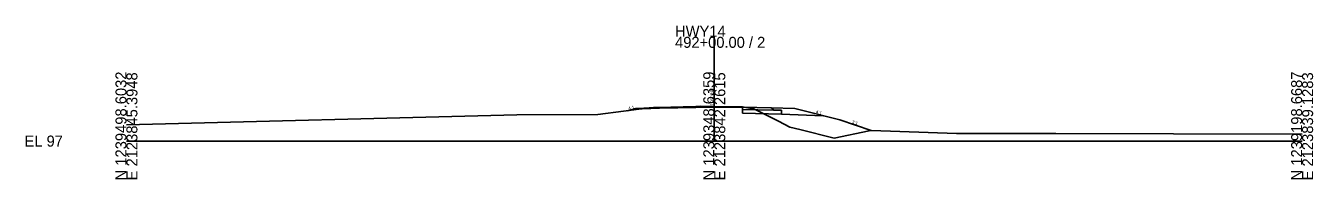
# Model space of a CAD drawing. Extents: x -26 to 303, y -10 to 11521.
# Drawn here: x -25.7 to 302.8, y 3490.3 to 3529.3 of the extents above; entities that cross this region are included whole.
import ezdxf

# ---------------------------------------------------------------- set-up
doc = ezdxf.new("R2010")
doc.units = 0
for name, color, linetype in [('XS_CELL', 7, 'Continuous'), ('XS_P_FINISHED_GRADE', 7, 'Continuous'), ('XS_P_SUBGRADE_GRANULAR', 7, 'Continuous'), ('XS_P_SUBGRADE_LEVELING', 7, 'Continuous'), ('XS_P_SUBGRADE_PAVEMENT', 7, 'Continuous'), ('XS_P_TX_FS_BS', 7, 'Continuous'), ('XS_X_GROUND', 7, 'Continuous'), ('XS_X_GROUND_TX', 7, 'Continuous')]:
    doc.layers.add(name, color=color, linetype=linetype)

msp = doc.modelspace()

# ---------------------------------------------------------------- linework, layer by layer
at = {"layer": 'XS_CELL'}
for p, q in [((150, 3500), (150, 3526.52)), ((0, 3500), (150, 3500)), ((150, 3500), (300, 3500))]:
    msp.add_line(p, q, dxfattribs=at)
at = {"layer": 'XS_P_FINISHED_GRADE'}
for p, q in [((150, 3508.78), (136, 3508.5)), ((150, 3508.78), (164.53, 3508.49)), ((130, 3508.26), (127.83, 3507.72)), ((136, 3508.5), (130, 3508.26)), ((164.53, 3508.49), (170.53, 3508.25)), ((170.53, 3508.25), (182, 3505.39)), ((182, 3505.39), (190.04, 3502.7))]:
    msp.add_line(p, q, dxfattribs=at)
at = {"layer": 'XS_P_SUBGRADE_GRANULAR'}
for p, q in [((136, 3508.38), (129.4, 3508.12)), ((157.24, 3508.06), (157.24, 3507.06)), ((157.24, 3507.06), (167.15, 3506.86)), ((165.15, 3507.9), (167.15, 3507.86)), ((167.15, 3506.86), (167.15, 3507.86)), ((167.15, 3506.86), (177.82, 3506.43))]:
    msp.add_line(p, q, dxfattribs=at)
at = {"layer": 'XS_P_SUBGRADE_LEVELING'}
for p, q in [((150, 3508.66), (136, 3508.38)), ((136, 3508.38), (136, 3508.5)), ((150, 3508.66), (157.24, 3508.51))]:
    msp.add_line(p, q, dxfattribs=at)
at = {"layer": 'XS_P_SUBGRADE_PAVEMENT'}
for p, q in [((157.24, 3508.64), (157.24, 3508.51)), ((157.24, 3508.06), (157.24, 3508.51)), ((157.24, 3508.06), (165.15, 3507.9)), ((164.53, 3508.49), (165.01, 3508.14)), ((165.01, 3508.14), (165.15, 3507.9))]:
    msp.add_line(p, q, dxfattribs=at)
at = {"layer": 'XS_X_GROUND'}
for p, q in [((135.7, 3508.58), (145.27, 3508.8)), ((145.27, 3508.8), (146.54, 3508.84)), ((146.54, 3508.84), (148.88, 3508.8)), ((148.88, 3508.8), (150, 3508.78)), ((150, 3508.78), (157.24, 3508.67)), ((0, 3504.13), (99.65, 3506.71)), ((99.65, 3506.71), (120.28, 3506.77)), ((120.28, 3506.77), (133.42, 3508.43)), ((133.42, 3508.43), (134.52, 3508.5)), ((134.52, 3508.5), (135.7, 3508.58)), ((157.24, 3508.67), (158.07, 3508.54)), ((158.07, 3508.54), (160.12, 3508.21)), ((160.12, 3508.21), (166.36, 3505.07)), ((166.36, 3505.07), (169.31, 3503.56)), ((169.31, 3503.56), (171.82, 3502.93)), ((171.82, 3502.93), (180.62, 3500.76)), ((180.62, 3500.76), (189.51, 3502.59)), ((189.51, 3502.59), (190.16, 3502.73)), ((190.16, 3502.73), (211.81, 3501.94)), ((211.81, 3501.94), (237.15, 3501.92)), ((237.15, 3501.92), (267.18, 3501.83)), ((267.18, 3501.83), (300, 3501.74))]:
    msp.add_line(p, q, dxfattribs=at)

# ---------------------------------------------------------------- texts
at = {"layer": 'XS_CELL'}
for s, p in [('HWY14', (140, 3526.52)), ('492+00.00 / 2', (140, 3523.72)), ('EL 97', (-26, 3498.6))]:
    msp.add_text(s, height=2.8, dxfattribs=at).set_placement(p)
for s, p in [('N 1239498.6032', (0, 3490)), ('E 2123845.3948', (2.8, 3490)), ('N 1239348.6359', (150, 3490)), ('E 2123842.2615', (152.8, 3490)), ('N 1239198.6687', (300, 3490)), ('E 2123839.1283', (302.8, 3490))]:
    msp.add_text(s, height=2.8, rotation=90, dxfattribs=at).set_placement(p)
at = {"layer": 'XS_P_TX_FS_BS'}
for s, rotation, p in [('4:1', 14.0362, (128.18, 3507.9)), ('4:1', 345.9638, (175.87, 3507.09)), ('3:1', 341.5651, (185.05, 3504.58))]:
    msp.add_text(s, height=0.8, rotation=rotation, dxfattribs=at).set_placement(p)
at = {"layer": 'XS_X_GROUND_TX'}
msp.add_text('105.78', height=1, rotation=90, dxfattribs=at).set_placement((150, 3508.88))

doc.saveas('drawing.dxf')
